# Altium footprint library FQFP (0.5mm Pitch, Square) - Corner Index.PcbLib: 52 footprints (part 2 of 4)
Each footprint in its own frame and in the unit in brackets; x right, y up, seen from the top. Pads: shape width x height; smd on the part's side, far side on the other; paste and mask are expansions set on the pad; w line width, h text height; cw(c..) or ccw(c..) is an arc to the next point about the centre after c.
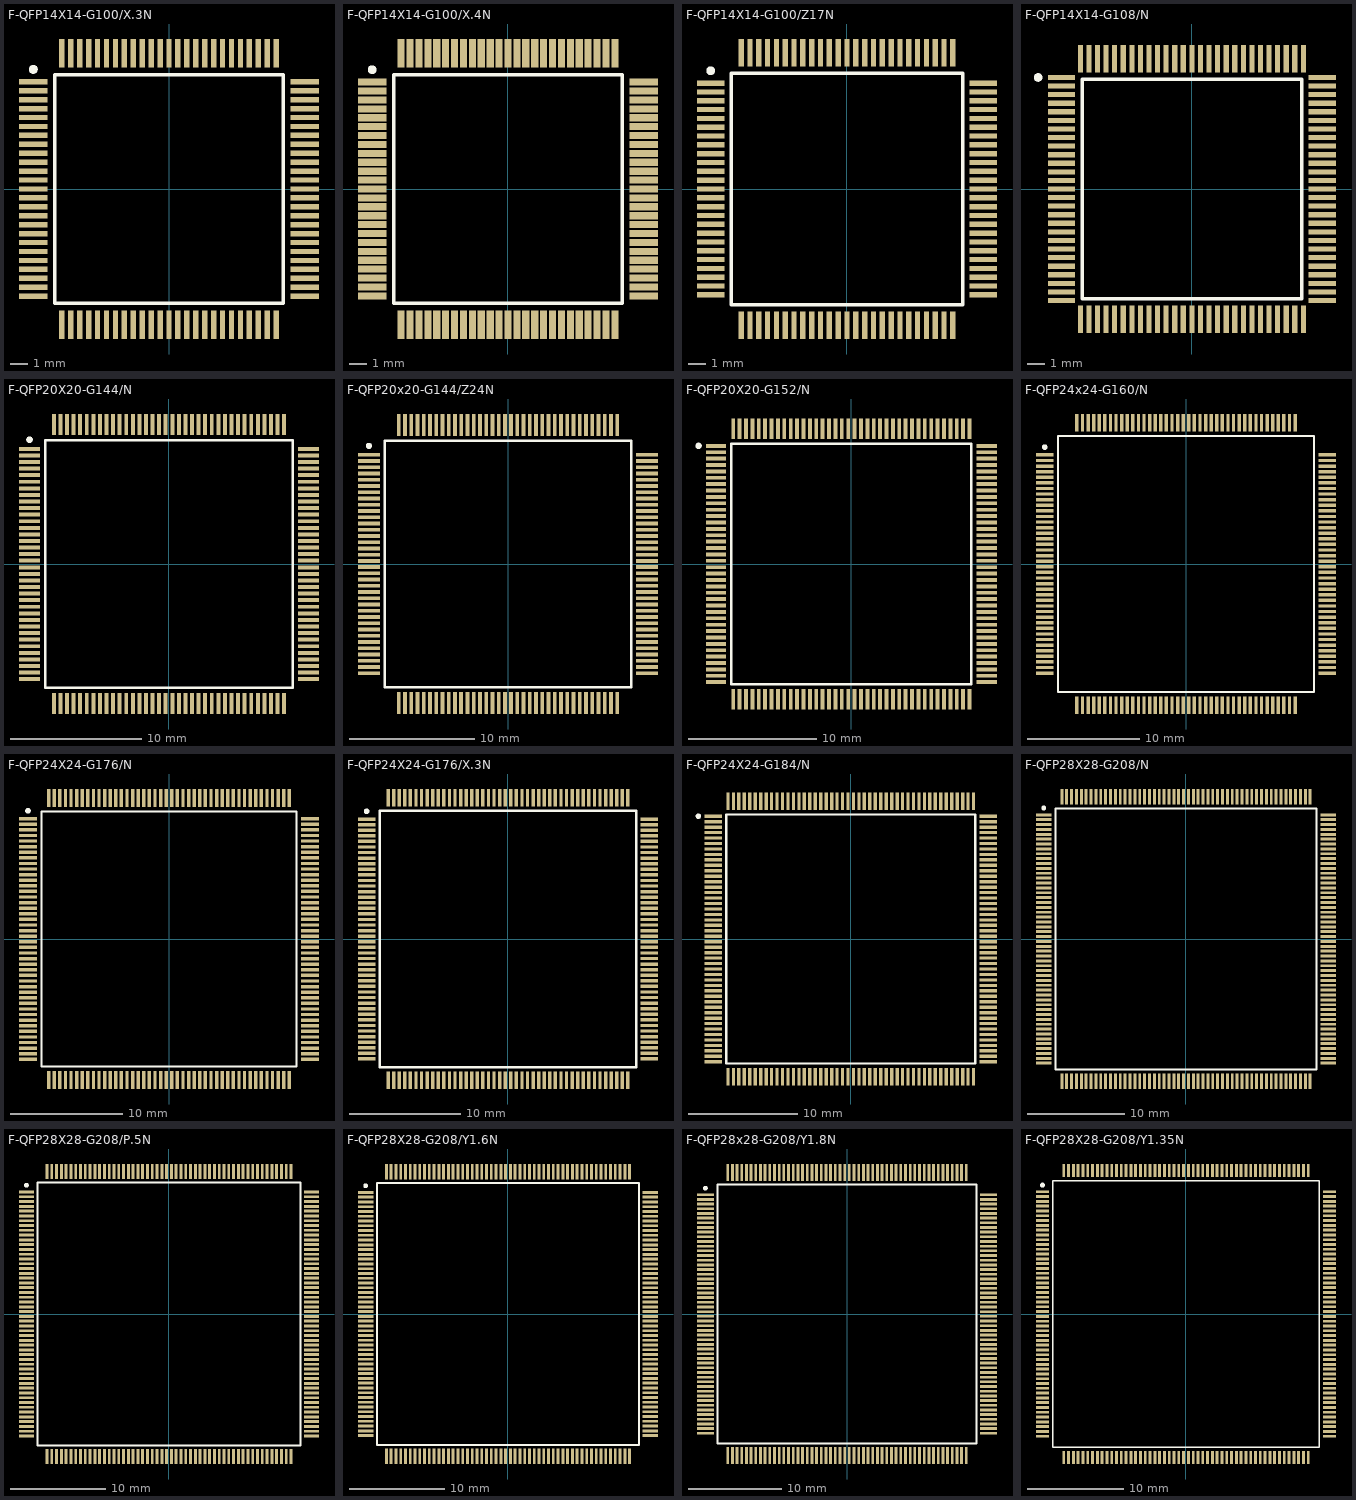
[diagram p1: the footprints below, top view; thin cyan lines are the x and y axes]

## F-QFP14X14-G100/X.3N [mm]
pads (100):
  rect 1.6x0.3 smd: 1(-7.6,6) 2(-7.6,5.5) 3(-7.6,5) 4(-7.6,4.5) 5(-7.6,4) 6(-7.6,3.5) 7(-7.6,3) 8(-7.6,2.5) 9(-7.6,2) 10(-7.6,1.5) 11(-7.6,1) 12(-7.6,0.5) 13(-7.6,0) 14(-7.6,-0.5) 15(-7.6,-1) 16(-7.6,-1.5) 17(-7.6,-2) 18(-7.6,-2.5) 19(-7.6,-3) 20(-7.6,-3.5) 21(-7.6,-4) 22(-7.6,-4.5) 23(-7.6,-5) 24(-7.6,-5.5) 25(-7.6,-6) 51(7.6,-6) 52(7.6,-5.5) 53(7.6,-5) 54(7.6,-4.5) 55(7.6,-4) 56(7.6,-3.5) 57(7.6,-3) 58(7.6,-2.5) 59(7.6,-2) 60(7.6,-1.5) 61(7.6,-1) 62(7.6,-0.5) 63(7.6,0) 64(7.6,0.5) 65(7.6,1) 66(7.6,1.5) 67(7.6,2) 68(7.6,2.5) 69(7.6,3) 70(7.6,3.5) 71(7.6,4) 72(7.6,4.5) 73(7.6,5) 74(7.6,5.5) 75(7.6,6)
  rect 0.3x1.6 smd: 26(-6,-7.6) 27(-5.5,-7.6) 28(-5,-7.6) 29(-4.5,-7.6) 30(-4,-7.6) 31(-3.5,-7.6) 32(-3,-7.6) 33(-2.5,-7.6) 34(-2,-7.6) 35(-1.5,-7.6) 36(-1,-7.6) 37(-0.5,-7.6) 38(0,-7.6) 39(0.5,-7.6) 40(1,-7.6) 41(1.5,-7.6) 42(2,-7.6) 43(2.5,-7.6) 44(3,-7.6) 45(3.5,-7.6) 46(4,-7.6) 47(4.5,-7.6) 48(5,-7.6) 49(5.5,-7.6) 50(6,-7.6) 76(6,7.6) 77(5.5,7.6) 78(5,7.6) 79(4.5,7.6) 80(4,7.6) 81(3.5,7.6) 82(3,7.6) 83(2.5,7.6) 84(2,7.6) 85(1.5,7.6) 86(1,7.6) 87(0.5,7.6) 88(0,7.6) 89(-0.5,7.6) 90(-1,7.6) 91(-1.5,7.6) 92(-2,7.6) 93(-2.5,7.6) 94(-3,7.6) 95(-3.5,7.6) 96(-4,7.6) 97(-4.5,7.6) 98(-5,7.6) 99(-5.5,7.6) 100(-6,7.6)
Top Overlay:
  circle w0.25: c-7.6,6.7 r0.125
  lines w0.2: -6.4,-6.4 6.4,-6.4 6.4,6.4 -6.4,6.4 -6.4,-6.4

## F-QFP14X14-G100/X.4N [mm]
pads (100):
  rect 1.6x0.4 smd: 1(-7.625,6) 2(-7.625,5.5) 3(-7.625,5) 4(-7.625,4.5) 5(-7.625,4) 6(-7.625,3.5) 7(-7.625,3) 8(-7.625,2.5) 9(-7.625,2) 10(-7.625,1.5) 11(-7.625,1) 12(-7.625,0.5) 13(-7.625,0) 14(-7.625,-0.5) 15(-7.625,-1) 16(-7.625,-1.5) 17(-7.625,-2) 18(-7.625,-2.5) 19(-7.625,-3) 20(-7.625,-3.5) 21(-7.625,-4) 22(-7.625,-4.5) 23(-7.625,-5) 24(-7.625,-5.5) 25(-7.625,-6) 51(7.625,-6) 52(7.625,-5.5) 53(7.625,-5) 54(7.625,-4.5) 55(7.625,-4) 56(7.625,-3.5) 57(7.625,-3) 58(7.625,-2.5) 59(7.625,-2) 60(7.625,-1.5) 61(7.625,-1) 62(7.625,-0.5) 63(7.625,0) 64(7.625,0.5) 65(7.625,1) 66(7.625,1.5) 67(7.625,2) 68(7.625,2.5) 69(7.625,3) 70(7.625,3.5) 71(7.625,4) 72(7.625,4.5) 73(7.625,5) 74(7.625,5.5) 75(7.625,6)
  rect 0.4x1.6 smd: 26(-6,-7.625) 27(-5.5,-7.625) 28(-5,-7.625) 29(-4.5,-7.625) 30(-4,-7.625) 31(-3.5,-7.625) 32(-3,-7.625) 33(-2.5,-7.625) 34(-2,-7.625) 35(-1.5,-7.625) 36(-1,-7.625) 37(-0.5,-7.625) 38(0,-7.625) 39(0.5,-7.625) 40(1,-7.625) 41(1.5,-7.625) 42(2,-7.625) 43(2.5,-7.625) 44(3,-7.625) 45(3.5,-7.625) 46(4,-7.625) 47(4.5,-7.625) 48(5,-7.625) 49(5.5,-7.625) 50(6,-7.625) 76(6,7.625) 77(5.5,7.625) 78(5,7.625) 79(4.5,7.625) 80(4,7.625) 81(3.5,7.625) 82(3,7.625) 83(2.5,7.625) 84(2,7.625) 85(1.5,7.625) 86(1,7.625) 87(0.5,7.625) 88(0,7.625) 89(-0.5,7.625) 90(-1,7.625) 91(-1.5,7.625) 92(-2,7.625) 93(-2.5,7.625) 94(-3,7.625) 95(-3.5,7.625) 96(-4,7.625) 97(-4.5,7.625) 98(-5,7.625) 99(-5.5,7.625) 100(-6,7.625)
Top Overlay:
  circle w0.25: c-7.625,6.7 r0.125
  lines w0.2: -6.425,-6.425 6.425,-6.425 6.425,6.425 -6.425,6.425 -6.425,-6.425

## F-QFP14X14-G100/Z17N [mm]
pads (100):
  rect 1.55x0.3 smd: 1(-7.725,6) 2(-7.725,5.5) 3(-7.725,5) 4(-7.725,4.5) 5(-7.725,4) 6(-7.725,3.5) 7(-7.725,3) 8(-7.725,2.5) 9(-7.725,2) 10(-7.725,1.5) 11(-7.725,1) 12(-7.725,0.5) 13(-7.725,0) 14(-7.725,-0.5) 15(-7.725,-1) 16(-7.725,-1.5) 17(-7.725,-2) 18(-7.725,-2.5) 19(-7.725,-3) 20(-7.725,-3.5) 21(-7.725,-4) 22(-7.725,-4.5) 23(-7.725,-5) 24(-7.725,-5.5) 25(-7.725,-6) 51(7.725,-6) 52(7.725,-5.5) 53(7.725,-5) 54(7.725,-4.5) 55(7.725,-4) 56(7.725,-3.5) 57(7.725,-3) 58(7.725,-2.5) 59(7.725,-2) 60(7.725,-1.5) 61(7.725,-1) 62(7.725,-0.5) 63(7.725,0) 64(7.725,0.5) 65(7.725,1) 66(7.725,1.5) 67(7.725,2) 68(7.725,2.5) 69(7.725,3) 70(7.725,3.5) 71(7.725,4) 72(7.725,4.5) 73(7.725,5) 74(7.725,5.5) 75(7.725,6)
  rect 0.3x1.55 smd: 26(-6,-7.725) 27(-5.5,-7.725) 28(-5,-7.725) 29(-4.5,-7.725) 30(-4,-7.725) 31(-3.5,-7.725) 32(-3,-7.725) 33(-2.5,-7.725) 34(-2,-7.725) 35(-1.5,-7.725) 36(-1,-7.725) 37(-0.5,-7.725) 38(0,-7.725) 39(0.5,-7.725) 40(1,-7.725) 41(1.5,-7.725) 42(2,-7.725) 43(2.5,-7.725) 44(3,-7.725) 45(3.5,-7.725) 46(4,-7.725) 47(4.5,-7.725) 48(5,-7.725) 49(5.5,-7.725) 50(6,-7.725) 76(6,7.725) 77(5.5,7.725) 78(5,7.725) 79(4.5,7.725) 80(4,7.725) 81(3.5,7.725) 82(3,7.725) 83(2.5,7.725) 84(2,7.725) 85(1.5,7.725) 86(1,7.725) 87(0.5,7.725) 88(0,7.725) 89(-0.5,7.725) 90(-1,7.725) 91(-1.5,7.725) 92(-2,7.725) 93(-2.5,7.725) 94(-3,7.725) 95(-3.5,7.725) 96(-4,7.725) 97(-4.5,7.725) 98(-5,7.725) 99(-5.5,7.725) 100(-6,7.725)
Top Overlay:
  circle w0.25: c-7.725,6.7 r0.125
  lines w0.2: -6.55,-6.55 6.55,-6.55 6.55,6.55 -6.55,6.55 -6.55,-6.55

## F-QFP14X14-G108/N [mm]
pads (108):
  rect 1.6x0.3 smd: 1(-7.6,6.5) 2(-7.6,6) 3(-7.6,5.5) 4(-7.6,5) 5(-7.6,4.5) 6(-7.6,4) 7(-7.6,3.5) 8(-7.6,3) 9(-7.6,2.5) 10(-7.6,2) 11(-7.6,1.5) 12(-7.6,1) 13(-7.6,0.5) 14(-7.6,0) 15(-7.6,-0.5) 16(-7.6,-1) 17(-7.6,-1.5) 18(-7.6,-2) 19(-7.6,-2.5) 20(-7.6,-3) 21(-7.6,-3.5) 22(-7.6,-4) 23(-7.6,-4.5) 24(-7.6,-5) 25(-7.6,-5.5) 26(-7.6,-6) 27(-7.6,-6.5) 55(7.6,-6.5) 56(7.6,-6) 57(7.6,-5.5) 58(7.6,-5) 59(7.6,-4.5) 60(7.6,-4) 61(7.6,-3.5) 62(7.6,-3) 63(7.6,-2.5) 64(7.6,-2) 65(7.6,-1.5) 66(7.6,-1) 67(7.6,-0.5) 68(7.6,0) 69(7.6,0.5) 70(7.6,1) 71(7.6,1.5) 72(7.6,2) 73(7.6,2.5) 74(7.6,3) 75(7.6,3.5) 76(7.6,4) 77(7.6,4.5) 78(7.6,5) 79(7.6,5.5) 80(7.6,6) 81(7.6,6.5)
  rect 0.3x1.6 smd: 28(-6.5,-7.6) 29(-6,-7.6) 30(-5.5,-7.6) 31(-5,-7.6) 32(-4.5,-7.6) 33(-4,-7.6) 34(-3.5,-7.6) 35(-3,-7.6) 36(-2.5,-7.6) 37(-2,-7.6) 38(-1.5,-7.6) 39(-1,-7.6) 40(-0.5,-7.6) 41(0,-7.6) 42(0.5,-7.6) 43(1,-7.6) 44(1.5,-7.6) 45(2,-7.6) 46(2.5,-7.6) 47(3,-7.6) 48(3.5,-7.6) 49(4,-7.6) 50(4.5,-7.6) 51(5,-7.6) 52(5.5,-7.6) 53(6,-7.6) 54(6.5,-7.6) 82(6.5,7.6) 83(6,7.6) 84(5.5,7.6) 85(5,7.6) 86(4.5,7.6) 87(4,7.6) 88(3.5,7.6) 89(3,7.6) 90(2.5,7.6) 91(2,7.6) 92(1.5,7.6) 93(1,7.6) 94(0.5,7.6) 95(0,7.6) 96(-0.5,7.6) 97(-1,7.6) 98(-1.5,7.6) 99(-2,7.6) 100(-2.5,7.6) 101(-3,7.6) 102(-3.5,7.6) 103(-4,7.6) 104(-4.5,7.6) 105(-5,7.6) 106(-5.5,7.6) 107(-6,7.6) 108(-6.5,7.6)
Top Overlay:
  circle w0.25: c-8.96,6.5 r0.125
  lines w0.2: -6.4,-6.4 -6.4,6.4 6.4,6.4 6.4,-6.4 -6.4,-6.4

## F-QFP20X20-G144/N [mm]
pads (144):
  rect 1.6x0.3 smd: 1(-10.6,8.75) 2(-10.6,8.25) 3(-10.6,7.75) 4(-10.6,7.25) 5(-10.6,6.75) 6(-10.6,6.25) 7(-10.6,5.75) 8(-10.6,5.25) 9(-10.6,4.75) 10(-10.6,4.25) 11(-10.6,3.75) 12(-10.6,3.25) 13(-10.6,2.75) 14(-10.6,2.25) 15(-10.6,1.75) 16(-10.6,1.25) 17(-10.6,0.75) 18(-10.6,0.25) 19(-10.6,-0.25) 20(-10.6,-0.75) 21(-10.6,-1.25) 22(-10.6,-1.75) 23(-10.6,-2.25) 24(-10.6,-2.75) 25(-10.6,-3.25) 26(-10.6,-3.75) 27(-10.6,-4.25) 28(-10.6,-4.75) 29(-10.6,-5.25) 30(-10.6,-5.75) 31(-10.6,-6.25) 32(-10.6,-6.75) 33(-10.6,-7.25) 34(-10.6,-7.75) 35(-10.6,-8.25) 36(-10.6,-8.75) 73(10.6,-8.75) 74(10.6,-8.25) 75(10.6,-7.75) 76(10.6,-7.25) 77(10.6,-6.75) 78(10.6,-6.25) 79(10.6,-5.75) 80(10.6,-5.25) 81(10.6,-4.75) 82(10.6,-4.25) 83(10.6,-3.75) 84(10.6,-3.25) 85(10.6,-2.75) 86(10.6,-2.25) 87(10.6,-1.75) 88(10.6,-1.25) 89(10.6,-0.75) 90(10.6,-0.25) 91(10.6,0.25) 92(10.6,0.75) 93(10.6,1.25) 94(10.6,1.75) 95(10.6,2.25) 96(10.6,2.75) 97(10.6,3.25) 98(10.6,3.75) 99(10.6,4.25) 100(10.6,4.75) 101(10.6,5.25) 102(10.6,5.75) 103(10.6,6.25) 104(10.6,6.75) 105(10.6,7.25) 106(10.6,7.75) 107(10.6,8.25) 108(10.6,8.75)
  rect 0.3x1.6 smd: 37(-8.75,-10.6) 38(-8.25,-10.6) 39(-7.75,-10.6) 40(-7.25,-10.6) 41(-6.75,-10.6) 42(-6.25,-10.6) 43(-5.75,-10.6) 44(-5.25,-10.6) 45(-4.75,-10.6) 46(-4.25,-10.6) 47(-3.75,-10.6) 48(-3.25,-10.6) 49(-2.75,-10.6) 50(-2.25,-10.6) 51(-1.75,-10.6) 52(-1.25,-10.6) 53(-0.75,-10.6) 54(-0.25,-10.6) 55(0.25,-10.6) 56(0.75,-10.6) 57(1.25,-10.6) 58(1.75,-10.6) 59(2.25,-10.6) 60(2.75,-10.6) 61(3.25,-10.6) 62(3.75,-10.6) 63(4.25,-10.6) 64(4.75,-10.6) 65(5.25,-10.6) 66(5.75,-10.6) 67(6.25,-10.6) 68(6.75,-10.6) 69(7.25,-10.6) 70(7.75,-10.6) 71(8.25,-10.6) 72(8.75,-10.6) 109(8.75,10.6) 110(8.25,10.6) 111(7.75,10.6) 112(7.25,10.6) 113(6.75,10.6) 114(6.25,10.6) 115(5.75,10.6) 116(5.25,10.6) 117(4.75,10.6) 118(4.25,10.6) 119(3.75,10.6) 120(3.25,10.6) 121(2.75,10.6) 122(2.25,10.6) 123(1.75,10.6) 124(1.25,10.6) 125(0.75,10.6) 126(0.25,10.6) 127(-0.25,10.6) 128(-0.75,10.6) 129(-1.25,10.6) 130(-1.75,10.6) 131(-2.25,10.6) 132(-2.75,10.6) 133(-3.25,10.6) 134(-3.75,10.6) 135(-4.25,10.6) 136(-4.75,10.6) 137(-5.25,10.6) 138(-5.75,10.6) 139(-6.25,10.6) 140(-6.75,10.6) 141(-7.25,10.6) 142(-7.75,10.6) 143(-8.25,10.6) 144(-8.75,10.6)
Top Overlay:
  circle w0.25: c-10.6,9.45 r0.125
  lines w0.2: -9.4,-9.4 -9.4,9.4 9.4,9.4 9.4,-9.4 -9.4,-9.4

## F-QFP20x20-G144/Z24N [mm]
pads (144):
  rect 1.75x0.3 smd: 1(-11.125,8.75) 2(-11.125,8.25) 3(-11.125,7.75) 4(-11.125,7.25) 5(-11.125,6.75) 6(-11.125,6.25) 7(-11.125,5.75) 8(-11.125,5.25) 9(-11.125,4.75) 10(-11.125,4.25) 11(-11.125,3.75) 12(-11.125,3.25) 13(-11.125,2.75) 14(-11.125,2.25) 15(-11.125,1.75) 16(-11.125,1.25) 17(-11.125,0.75) 18(-11.125,0.25) 19(-11.125,-0.25) 20(-11.125,-0.75) 21(-11.125,-1.25) 22(-11.125,-1.75) 23(-11.125,-2.25) 24(-11.125,-2.75) 25(-11.125,-3.25) 26(-11.125,-3.75) 27(-11.125,-4.25) 28(-11.125,-4.75) 29(-11.125,-5.25) 30(-11.125,-5.75) 31(-11.125,-6.25) 32(-11.125,-6.75) 33(-11.125,-7.25) 34(-11.125,-7.75) 35(-11.125,-8.25) 36(-11.125,-8.75) 73(11.125,-8.75) 74(11.125,-8.25) 75(11.125,-7.75) 76(11.125,-7.25) 77(11.125,-6.75) 78(11.125,-6.25) 79(11.125,-5.75) 80(11.125,-5.25) 81(11.125,-4.75) 82(11.125,-4.25) 83(11.125,-3.75) 84(11.125,-3.25) 85(11.125,-2.75) 86(11.125,-2.25) 87(11.125,-1.75) 88(11.125,-1.25) 89(11.125,-0.75) 90(11.125,-0.25) 91(11.125,0.25) 92(11.125,0.75) 93(11.125,1.25) 94(11.125,1.75) 95(11.125,2.25) 96(11.125,2.75) 97(11.125,3.25) 98(11.125,3.75) 99(11.125,4.25) 100(11.125,4.75) 101(11.125,5.25) 102(11.125,5.75) 103(11.125,6.25) 104(11.125,6.75) 105(11.125,7.25) 106(11.125,7.75) 107(11.125,8.25) 108(11.125,8.75)
  rect 0.3x1.75 smd: 37(-8.75,-11.125) 38(-8.25,-11.125) 39(-7.75,-11.125) 40(-7.25,-11.125) 41(-6.75,-11.125) 42(-6.25,-11.125) 43(-5.75,-11.125) 44(-5.25,-11.125) 45(-4.75,-11.125) 46(-4.25,-11.125) 47(-3.75,-11.125) 48(-3.25,-11.125) 49(-2.75,-11.125) 50(-2.25,-11.125) 51(-1.75,-11.125) 52(-1.25,-11.125) 53(-0.75,-11.125) 54(-0.25,-11.125) 55(0.25,-11.125) 56(0.75,-11.125) 57(1.25,-11.125) 58(1.75,-11.125) 59(2.25,-11.125) 60(2.75,-11.125) 61(3.25,-11.125) 62(3.75,-11.125) 63(4.25,-11.125) 64(4.75,-11.125) 65(5.25,-11.125) 66(5.75,-11.125) 67(6.25,-11.125) 68(6.75,-11.125) 69(7.25,-11.125) 70(7.75,-11.125) 71(8.25,-11.125) 72(8.75,-11.125) 109(8.75,11.125) 110(8.25,11.125) 111(7.75,11.125) 112(7.25,11.125) 113(6.75,11.125) 114(6.25,11.125) 115(5.75,11.125) 116(5.25,11.125) 117(4.75,11.125) 118(4.25,11.125) 119(3.75,11.125) 120(3.25,11.125) 121(2.75,11.125) 122(2.25,11.125) 123(1.75,11.125) 124(1.25,11.125) 125(0.75,11.125) 126(0.25,11.125) 127(-0.25,11.125) 128(-0.75,11.125) 129(-1.25,11.125) 130(-1.75,11.125) 131(-2.25,11.125) 132(-2.75,11.125) 133(-3.25,11.125) 134(-3.75,11.125) 135(-4.25,11.125) 136(-4.75,11.125) 137(-5.25,11.125) 138(-5.75,11.125) 139(-6.25,11.125) 140(-6.75,11.125) 141(-7.25,11.125) 142(-7.75,11.125) 143(-8.25,11.125) 144(-8.75,11.125)
Top Overlay:
  circle w0.25: c-11.13,9.45 r0.125
  lines w0.2: -9.85,-9.85 9.85,-9.85 9.85,9.85 -9.85,9.85 -9.85,-9.85

## F-QFP20X20-G152/N [mm]
pads (152):
  rect 1.6x0.3 smd: 1(-10.6,9.25) 2(-10.6,8.75) 3(-10.6,8.25) 4(-10.6,7.75) 5(-10.6,7.25) 6(-10.6,6.75) 7(-10.6,6.25) 8(-10.6,5.75) 9(-10.6,5.25) 10(-10.6,4.75) 11(-10.6,4.25) 12(-10.6,3.75) 13(-10.6,3.25) 14(-10.6,2.75) 15(-10.6,2.25) 16(-10.6,1.75) 17(-10.6,1.25) 18(-10.6,0.75) 19(-10.6,0.25) 20(-10.6,-0.25) 21(-10.6,-0.75) 22(-10.6,-1.25) 23(-10.6,-1.75) 24(-10.6,-2.25) 25(-10.6,-2.75) 26(-10.6,-3.25) 27(-10.6,-3.75) 28(-10.6,-4.25) 29(-10.6,-4.75) 30(-10.6,-5.25) 31(-10.6,-5.75) 32(-10.6,-6.25) 33(-10.6,-6.75) 34(-10.6,-7.25) 35(-10.6,-7.75) 36(-10.6,-8.25) 37(-10.6,-8.75) 38(-10.6,-9.25) 77(10.6,-9.25) 78(10.6,-8.75) 79(10.6,-8.25) 80(10.6,-7.75) 81(10.6,-7.25) 82(10.6,-6.75) 83(10.6,-6.25) 84(10.6,-5.75) 85(10.6,-5.25) 86(10.6,-4.75) 87(10.6,-4.25) 88(10.6,-3.75) 89(10.6,-3.25) 90(10.6,-2.75) 91(10.6,-2.25) 92(10.6,-1.75) 93(10.6,-1.25) 94(10.6,-0.75) 95(10.6,-0.25) 96(10.6,0.25) 97(10.6,0.75) 98(10.6,1.25) 99(10.6,1.75) 100(10.6,2.25) 101(10.6,2.75) 102(10.6,3.25) 103(10.6,3.75) 104(10.6,4.25) 105(10.6,4.75) 106(10.6,5.25) 107(10.6,5.75) 108(10.6,6.25) 109(10.6,6.75) 110(10.6,7.25) 111(10.6,7.75) 112(10.6,8.25) 113(10.6,8.75) 114(10.6,9.25)
  rect 0.3x1.6 smd: 39(-9.25,-10.6) 40(-8.75,-10.6) 41(-8.25,-10.6) 42(-7.75,-10.6) 43(-7.25,-10.6) 44(-6.75,-10.6) 45(-6.25,-10.6) 46(-5.75,-10.6) 47(-5.25,-10.6) 48(-4.75,-10.6) 49(-4.25,-10.6) 50(-3.75,-10.6) 51(-3.25,-10.6) 52(-2.75,-10.6) 53(-2.25,-10.6) 54(-1.75,-10.6) 55(-1.25,-10.6) 56(-0.75,-10.6) 57(-0.25,-10.6) 58(0.25,-10.6) 59(0.75,-10.6) 60(1.25,-10.6) 61(1.75,-10.6) 62(2.25,-10.6) 63(2.75,-10.6) 64(3.25,-10.6) 65(3.75,-10.6) 66(4.25,-10.6) 67(4.75,-10.6) 68(5.25,-10.6) 69(5.75,-10.6) 70(6.25,-10.6) 71(6.75,-10.6) 72(7.25,-10.6) 73(7.75,-10.6) 74(8.25,-10.6) 75(8.75,-10.6) 76(9.25,-10.6) 115(9.25,10.6) 116(8.75,10.6) 117(8.25,10.6) 118(7.75,10.6) 119(7.25,10.6) 120(6.75,10.6) 121(6.25,10.6) 122(5.75,10.6) 123(5.25,10.6) 124(4.75,10.6) 125(4.25,10.6) 126(3.75,10.6) 127(3.25,10.6) 128(2.75,10.6) 129(2.25,10.6) 130(1.75,10.6) 131(1.25,10.6) 132(0.75,10.6) 133(0.25,10.6) 134(-0.25,10.6) 135(-0.75,10.6) 136(-1.25,10.6) 137(-1.75,10.6) 138(-2.25,10.6) 139(-2.75,10.6) 140(-3.25,10.6) 141(-3.75,10.6) 142(-4.25,10.6) 143(-4.75,10.6) 144(-5.25,10.6) 145(-5.75,10.6) 146(-6.25,10.6) 147(-6.75,10.6) 148(-7.25,10.6) 149(-7.75,10.6) 150(-8.25,10.6) 151(-8.75,10.6) 152(-9.25,10.6)
Top Overlay:
  circle w0.25: c-11.96,9.25 r0.125
  lines w0.2: -9.4,-9.4 9.4,-9.4 9.4,9.4 -9.4,9.4 -9.4,-9.4

## F-QFP24x24-G160/N [mm]
pads (160):
  rect 1.55x0.3 smd: 1(-12.63,9.75) 2(-12.63,9.25) 3(-12.63,8.75) 4(-12.63,8.25) 5(-12.63,7.75) 6(-12.63,7.25) 7(-12.63,6.75) 8(-12.63,6.25) 9(-12.63,5.75) 10(-12.63,5.25) 11(-12.63,4.75) 12(-12.63,4.25) 13(-12.63,3.75) 14(-12.63,3.25) 15(-12.63,2.75) 16(-12.63,2.25) 17(-12.63,1.75) 18(-12.63,1.25) 19(-12.63,0.75) 20(-12.63,0.25) 21(-12.63,-0.25) 22(-12.63,-0.75) 23(-12.63,-1.25) 24(-12.63,-1.75) 25(-12.63,-2.25) 26(-12.63,-2.75) 27(-12.63,-3.25) 28(-12.63,-3.75) 29(-12.63,-4.25) 30(-12.63,-4.75) 31(-12.63,-5.25) 32(-12.63,-5.75) 33(-12.63,-6.25) 34(-12.63,-6.75) 35(-12.63,-7.25) 36(-12.63,-7.75) 37(-12.63,-8.25) 38(-12.63,-8.75) 39(-12.63,-9.25) 40(-12.63,-9.75) 81(12.63,-9.75) 82(12.63,-9.25) 83(12.63,-8.75) 84(12.63,-8.25) 85(12.63,-7.75) 86(12.63,-7.25) 87(12.63,-6.75) 88(12.63,-6.25) 89(12.63,-5.75) 90(12.63,-5.25) 91(12.63,-4.75) 92(12.63,-4.25) 93(12.63,-3.75) 94(12.63,-3.25) 95(12.63,-2.75) 96(12.63,-2.25) 97(12.63,-1.75) 98(12.63,-1.25) 99(12.63,-0.75) 100(12.63,-0.25) 101(12.63,0.25) 102(12.63,0.75) 103(12.63,1.25) 104(12.63,1.75) 105(12.63,2.25) 106(12.63,2.75) 107(12.63,3.25) 108(12.63,3.75) 109(12.63,4.25) 110(12.63,4.75) 111(12.63,5.25) 112(12.63,5.75) 113(12.63,6.25) 114(12.63,6.75) 115(12.63,7.25) 116(12.63,7.75) 117(12.63,8.25) 118(12.63,8.75) 119(12.63,9.25) 120(12.63,9.75)
  rect 0.3x1.55 smd: 41(-9.75,-12.63) 42(-9.25,-12.63) 43(-8.75,-12.63) 44(-8.25,-12.63) 45(-7.75,-12.63) 46(-7.25,-12.63) 47(-6.75,-12.63) 48(-6.25,-12.63) 49(-5.75,-12.63) 50(-5.25,-12.63) 51(-4.75,-12.63) 52(-4.25,-12.63) 53(-3.75,-12.63) 54(-3.25,-12.63) 55(-2.75,-12.63) 56(-2.25,-12.63) 57(-1.75,-12.63) 58(-1.25,-12.63) 59(-0.75,-12.63) 60(-0.25,-12.63) 61(0.25,-12.63) 62(0.75,-12.63) 63(1.25,-12.63) 64(1.75,-12.63) 65(2.25,-12.63) 66(2.75,-12.63) 67(3.25,-12.63) 68(3.75,-12.63) 69(4.25,-12.63) 70(4.75,-12.63) 71(5.25,-12.63) 72(5.75,-12.63) 73(6.25,-12.63) 74(6.75,-12.63) 75(7.25,-12.63) 76(7.75,-12.63) 77(8.25,-12.63) 78(8.75,-12.63) 79(9.25,-12.63) 80(9.75,-12.63) 121(9.75,12.63) 122(9.25,12.63) 123(8.75,12.63) 124(8.25,12.63) 125(7.75,12.63) 126(7.25,12.63) 127(6.75,12.63) 128(6.25,12.63) 129(5.75,12.63) 130(5.25,12.63) 131(4.75,12.63) 132(4.25,12.63) 133(3.75,12.63) 134(3.25,12.63) 135(2.75,12.63) 136(2.25,12.63) 137(1.75,12.63) 138(1.25,12.63) 139(0.75,12.63) 140(0.25,12.63) 141(-0.25,12.63) 142(-0.75,12.63) 143(-1.25,12.63) 144(-1.75,12.63) 145(-2.25,12.63) 146(-2.75,12.63) 147(-3.25,12.63) 148(-3.75,12.63) 149(-4.25,12.63) 150(-4.75,12.63) 151(-5.25,12.63) 152(-5.75,12.63) 153(-6.25,12.63) 154(-6.75,12.63) 155(-7.25,12.63) 156(-7.75,12.63) 157(-8.25,12.63) 158(-8.75,12.63) 159(-9.25,12.63) 160(-9.75,12.63)
Top Overlay:
  circle w0.25: c-12.63,10.45 r0.125
  lines w0.2: -11.45,-11.45 -11.45,11.45 11.45,11.45 11.45,-11.45 -11.45,-11.45

## F-QFP24X24-G176/N [mm]
pads (176):
  rect 1.6x0.3 smd: 1(-12.6,10.75) 2(-12.6,10.25) 3(-12.6,9.75) 4(-12.6,9.25) 5(-12.6,8.75) 6(-12.6,8.25) 7(-12.6,7.75) 8(-12.6,7.25) 9(-12.6,6.75) 10(-12.6,6.25) 11(-12.6,5.75) 12(-12.6,5.25) 13(-12.6,4.75) 14(-12.6,4.25) 15(-12.6,3.75) 16(-12.6,3.25) 17(-12.6,2.75) 18(-12.6,2.25) 19(-12.6,1.75) 20(-12.6,1.25) 21(-12.6,0.75) 22(-12.6,0.25) 23(-12.6,-0.25) 24(-12.6,-0.75) 25(-12.6,-1.25) 26(-12.6,-1.75) 27(-12.6,-2.25) 28(-12.6,-2.75) 29(-12.6,-3.25) 30(-12.6,-3.75) 31(-12.6,-4.25) 32(-12.6,-4.75) 33(-12.6,-5.25) 34(-12.6,-5.75) 35(-12.6,-6.25) 36(-12.6,-6.75) 37(-12.6,-7.25) 38(-12.6,-7.75) 39(-12.6,-8.25) 40(-12.6,-8.75) 41(-12.6,-9.25) 42(-12.6,-9.75) 43(-12.6,-10.25) 44(-12.6,-10.75) 89(12.6,-10.75) 90(12.6,-10.25) 91(12.6,-9.75) 92(12.6,-9.25) 93(12.6,-8.75) 94(12.6,-8.25) 95(12.6,-7.75) 96(12.6,-7.25) 97(12.6,-6.75) 98(12.6,-6.25) 99(12.6,-5.75) 100(12.6,-5.25) 101(12.6,-4.75) 102(12.6,-4.25) 103(12.6,-3.75) 104(12.6,-3.25) 105(12.6,-2.75) 106(12.6,-2.25) 107(12.6,-1.75) 108(12.6,-1.25) 109(12.6,-0.75) 110(12.6,-0.25) 111(12.6,0.25) 112(12.6,0.75) 113(12.6,1.25) 114(12.6,1.75) 115(12.6,2.25) 116(12.6,2.75) 117(12.6,3.25) 118(12.6,3.75) 119(12.6,4.25) 120(12.6,4.75) 121(12.6,5.25) 122(12.6,5.75) 123(12.6,6.25) 124(12.6,6.75) 125(12.6,7.25) 126(12.6,7.75) 127(12.6,8.25) 128(12.6,8.75) 129(12.6,9.25) 130(12.6,9.75) 131(12.6,10.25) 132(12.6,10.75)
  rect 0.3x1.6 smd: 45(-10.75,-12.6) 46(-10.25,-12.6) 47(-9.75,-12.6) 48(-9.25,-12.6) 49(-8.75,-12.6) 50(-8.25,-12.6) 51(-7.75,-12.6) 52(-7.25,-12.6) 53(-6.75,-12.6) 54(-6.25,-12.6) 55(-5.75,-12.6) 56(-5.25,-12.6) 57(-4.75,-12.6) 58(-4.25,-12.6) 59(-3.75,-12.6) 60(-3.25,-12.6) 61(-2.75,-12.6) 62(-2.25,-12.6) 63(-1.75,-12.6) 64(-1.25,-12.6) 65(-0.75,-12.6) 66(-0.25,-12.6) 67(0.25,-12.6) 68(0.75,-12.6) 69(1.25,-12.6) 70(1.75,-12.6) 71(2.25,-12.6) 72(2.75,-12.6) 73(3.25,-12.6) 74(3.75,-12.6) 75(4.25,-12.6) 76(4.75,-12.6) 77(5.25,-12.6) 78(5.75,-12.6) 79(6.25,-12.6) 80(6.75,-12.6) 81(7.25,-12.6) 82(7.75,-12.6) 83(8.25,-12.6) 84(8.75,-12.6) 85(9.25,-12.6) 86(9.75,-12.6) 87(10.25,-12.6) 88(10.75,-12.6) 133(10.75,12.6) 134(10.25,12.6) 135(9.75,12.6) 136(9.25,12.6) 137(8.75,12.6) 138(8.25,12.6) 139(7.75,12.6) 140(7.25,12.6) 141(6.75,12.6) 142(6.25,12.6) 143(5.75,12.6) 144(5.25,12.6) 145(4.75,12.6) 146(4.25,12.6) 147(3.75,12.6) 148(3.25,12.6) 149(2.75,12.6) 150(2.25,12.6) 151(1.75,12.6) 152(1.25,12.6) 153(0.75,12.6) 154(0.25,12.6) 155(-0.25,12.6) 156(-0.75,12.6) 157(-1.25,12.6) 158(-1.75,12.6) 159(-2.25,12.6) 160(-2.75,12.6) 161(-3.25,12.6) 162(-3.75,12.6) 163(-4.25,12.6) 164(-4.75,12.6) 165(-5.25,12.6) 166(-5.75,12.6) 167(-6.25,12.6) 168(-6.75,12.6) 169(-7.25,12.6) 170(-7.75,12.6) 171(-8.25,12.6) 172(-8.75,12.6) 173(-9.25,12.6) 174(-9.75,12.6) 175(-10.25,12.6) 176(-10.75,12.6)
Top Overlay:
  circle w0.25: c-12.6,11.45 r0.125
  lines w0.2: -11.4,-11.4 -11.4,11.4 11.4,11.4 11.4,-11.4 -11.4,-11.4

## F-QFP24X24-G176/X.3N [mm]
pads (176):
  rect 1.55x0.3 smd: 1(-12.675,10.75) 2(-12.675,10.25) 3(-12.675,9.75) 4(-12.675,9.25) 5(-12.675,8.75) 6(-12.675,8.25) 7(-12.675,7.75) 8(-12.675,7.25) 9(-12.675,6.75) 10(-12.675,6.25) 11(-12.675,5.75) 12(-12.675,5.25) 13(-12.675,4.75) 14(-12.675,4.25) 15(-12.675,3.75) 16(-12.675,3.25) 17(-12.675,2.75) 18(-12.675,2.25) 19(-12.675,1.75) 20(-12.675,1.25) 21(-12.675,0.75) 22(-12.675,0.25) 23(-12.675,-0.25) 24(-12.675,-0.75) 25(-12.675,-1.25) 26(-12.675,-1.75) 27(-12.675,-2.25) 28(-12.675,-2.75) 29(-12.675,-3.25) 30(-12.675,-3.75) 31(-12.675,-4.25) 32(-12.675,-4.75) 33(-12.675,-5.25) 34(-12.675,-5.75) 35(-12.675,-6.25) 36(-12.675,-6.75) 37(-12.675,-7.25) 38(-12.675,-7.75) 39(-12.675,-8.25) 40(-12.675,-8.75) 41(-12.675,-9.25) 42(-12.675,-9.75) 43(-12.675,-10.25) 44(-12.675,-10.75) 89(12.675,-10.75) 90(12.675,-10.25) 91(12.675,-9.75) 92(12.675,-9.25) 93(12.675,-8.75) 94(12.675,-8.25) 95(12.675,-7.75) 96(12.675,-7.25) 97(12.675,-6.75) 98(12.675,-6.25) 99(12.675,-5.75) 100(12.675,-5.25) 101(12.675,-4.75) 102(12.675,-4.25) 103(12.675,-3.75) 104(12.675,-3.25) 105(12.675,-2.75) 106(12.675,-2.25) 107(12.675,-1.75) 108(12.675,-1.25) 109(12.675,-0.75) 110(12.675,-0.25) 111(12.675,0.25) 112(12.675,0.75) 113(12.675,1.25) 114(12.675,1.75) 115(12.675,2.25) 116(12.675,2.75) 117(12.675,3.25) 118(12.675,3.75) 119(12.675,4.25) 120(12.675,4.75) 121(12.675,5.25) 122(12.675,5.75) 123(12.675,6.25) 124(12.675,6.75) 125(12.675,7.25) 126(12.675,7.75) 127(12.675,8.25) 128(12.675,8.75) 129(12.675,9.25) 130(12.675,9.75) 131(12.675,10.25) 132(12.675,10.75)
  rect 0.3x1.55 smd: 45(-10.75,-12.675) 46(-10.25,-12.675) 47(-9.75,-12.675) 48(-9.25,-12.675) 49(-8.75,-12.675) 50(-8.25,-12.675) 51(-7.75,-12.675) 52(-7.25,-12.675) 53(-6.75,-12.675) 54(-6.25,-12.675) 55(-5.75,-12.675) 56(-5.25,-12.675) 57(-4.75,-12.675) 58(-4.25,-12.675) 59(-3.75,-12.675) 60(-3.25,-12.675) 61(-2.75,-12.675) 62(-2.25,-12.675) 63(-1.75,-12.675) 64(-1.25,-12.675) 65(-0.75,-12.675) 66(-0.25,-12.675) 67(0.25,-12.675) 68(0.75,-12.675) 69(1.25,-12.675) 70(1.75,-12.675) 71(2.25,-12.675) 72(2.75,-12.675) 73(3.25,-12.675) 74(3.75,-12.675) 75(4.25,-12.675) 76(4.75,-12.675) 77(5.25,-12.675) 78(5.75,-12.675) 79(6.25,-12.675) 80(6.75,-12.675) 81(7.25,-12.675) 82(7.75,-12.675) 83(8.25,-12.675) 84(8.75,-12.675) 85(9.25,-12.675) 86(9.75,-12.675) 87(10.25,-12.675) 88(10.75,-12.675) 133(10.75,12.675) 134(10.25,12.675) 135(9.75,12.675) 136(9.25,12.675) 137(8.75,12.675) 138(8.25,12.675) 139(7.75,12.675) 140(7.25,12.675) 141(6.75,12.675) 142(6.25,12.675) 143(5.75,12.675) 144(5.25,12.675) 145(4.75,12.675) 146(4.25,12.675) 147(3.75,12.675) 148(3.25,12.675) 149(2.75,12.675) 150(2.25,12.675) 151(1.75,12.675) 152(1.25,12.675) 153(0.75,12.675) 154(0.25,12.675) 155(-0.25,12.675) 156(-0.75,12.675) 157(-1.25,12.675) 158(-1.75,12.675) 159(-2.25,12.675) 160(-2.75,12.675) 161(-3.25,12.675) 162(-3.75,12.675) 163(-4.25,12.675) 164(-4.75,12.675) 165(-5.25,12.675) 166(-5.75,12.675) 167(-6.25,12.675) 168(-6.75,12.675) 169(-7.25,12.675) 170(-7.75,12.675) 171(-8.25,12.675) 172(-8.75,12.675) 173(-9.25,12.675) 174(-9.75,12.675) 175(-10.25,12.675) 176(-10.75,12.675)
Top Overlay:
  circle w0.25: c-12.675,11.45 r0.125
  lines w0.2: -11.5,-11.5 -11.5,11.5 11.5,11.5 11.5,-11.5 -11.5,-11.5

## F-QFP24X24-G184/N [mm]
pads (184):
  rect 1.6x0.3 smd: 1(-12.6,11.25) 2(-12.6,10.75) 3(-12.6,10.25) 4(-12.6,9.75) 5(-12.6,9.25) 6(-12.6,8.75) 7(-12.6,8.25) 8(-12.6,7.75) 9(-12.6,7.25) 10(-12.6,6.75) 11(-12.6,6.25) 12(-12.6,5.75) 13(-12.6,5.25) 14(-12.6,4.75) 15(-12.6,4.25) 16(-12.6,3.75) 17(-12.6,3.25) 18(-12.6,2.75) 19(-12.6,2.25) 20(-12.6,1.75) 21(-12.6,1.25) 22(-12.6,0.75) 23(-12.6,0.25) 24(-12.6,-0.25) 25(-12.6,-0.75) 26(-12.6,-1.25) 27(-12.6,-1.75) 28(-12.6,-2.25) 29(-12.6,-2.75) 30(-12.6,-3.25) 31(-12.6,-3.75) 32(-12.6,-4.25) 33(-12.6,-4.75) 34(-12.6,-5.25) 35(-12.6,-5.75) 36(-12.6,-6.25) 37(-12.6,-6.75) 38(-12.6,-7.25) 39(-12.6,-7.75) 40(-12.6,-8.25) 41(-12.6,-8.75) 42(-12.6,-9.25) 43(-12.6,-9.75) 44(-12.6,-10.25) 45(-12.6,-10.75) 46(-12.6,-11.25) 93(12.6,-11.25) 94(12.6,-10.75) 95(12.6,-10.25) 96(12.6,-9.75) 97(12.6,-9.25) 98(12.6,-8.75) 99(12.6,-8.25) 100(12.6,-7.75) 101(12.6,-7.25) 102(12.6,-6.75) 103(12.6,-6.25) 104(12.6,-5.75) 105(12.6,-5.25) 106(12.6,-4.75) 107(12.6,-4.25) 108(12.6,-3.75) 109(12.6,-3.25) 110(12.6,-2.75) 111(12.6,-2.25) 112(12.6,-1.75) 113(12.6,-1.25) 114(12.6,-0.75) 115(12.6,-0.25) 116(12.6,0.25) 117(12.6,0.75) 118(12.6,1.25) 119(12.6,1.75) 120(12.6,2.25) 121(12.6,2.75) 122(12.6,3.25) 123(12.6,3.75) 124(12.6,4.25) 125(12.6,4.75) 126(12.6,5.25) 127(12.6,5.75) 128(12.6,6.25) 129(12.6,6.75) 130(12.6,7.25) 131(12.6,7.75) 132(12.6,8.25) 133(12.6,8.75) 134(12.6,9.25) 135(12.6,9.75) 136(12.6,10.25) 137(12.6,10.75) 138(12.6,11.25)
  rect 0.3x1.6 smd: 47(-11.25,-12.6) 48(-10.75,-12.6) 49(-10.25,-12.6) 50(-9.75,-12.6) 51(-9.25,-12.6) 52(-8.75,-12.6) 53(-8.25,-12.6) 54(-7.75,-12.6) 55(-7.25,-12.6) 56(-6.75,-12.6) 57(-6.25,-12.6) 58(-5.75,-12.6) 59(-5.25,-12.6) 60(-4.75,-12.6) 61(-4.25,-12.6) 62(-3.75,-12.6) 63(-3.25,-12.6) 64(-2.75,-12.6) 65(-2.25,-12.6) 66(-1.75,-12.6) 67(-1.25,-12.6) 68(-0.75,-12.6) 69(-0.25,-12.6) 70(0.25,-12.6) 71(0.75,-12.6) 72(1.25,-12.6) 73(1.75,-12.6) 74(2.25,-12.6) 75(2.75,-12.6) 76(3.25,-12.6) 77(3.75,-12.6) 78(4.25,-12.6) 79(4.75,-12.6) 80(5.25,-12.6) 81(5.75,-12.6) 82(6.25,-12.6) 83(6.75,-12.6) 84(7.25,-12.6) 85(7.75,-12.6) 86(8.25,-12.6) 87(8.75,-12.6) 88(9.25,-12.6) 89(9.75,-12.6) 90(10.25,-12.6) 91(10.75,-12.6) 92(11.25,-12.6) 139(11.25,12.6) 140(10.75,12.6) 141(10.25,12.6) 142(9.75,12.6) 143(9.25,12.6) 144(8.75,12.6) 145(8.25,12.6) 146(7.75,12.6) 147(7.25,12.6) 148(6.75,12.6) 149(6.25,12.6) 150(5.75,12.6) 151(5.25,12.6) 152(4.75,12.6) 153(4.25,12.6) 154(3.75,12.6) 155(3.25,12.6) 156(2.75,12.6) 157(2.25,12.6) 158(1.75,12.6) 159(1.25,12.6) 160(0.75,12.6) 161(0.25,12.6) 162(-0.25,12.6) 163(-0.75,12.6) 164(-1.25,12.6) 165(-1.75,12.6) 166(-2.25,12.6) 167(-2.75,12.6) 168(-3.25,12.6) 169(-3.75,12.6) 170(-4.25,12.6) 171(-4.75,12.6) 172(-5.25,12.6) 173(-5.75,12.6) 174(-6.25,12.6) 175(-6.75,12.6) 176(-7.25,12.6) 177(-7.75,12.6) 178(-8.25,12.6) 179(-8.75,12.6) 180(-9.25,12.6) 181(-9.75,12.6) 182(-10.25,12.6) 183(-10.75,12.6) 184(-11.25,12.6)
Top Overlay:
  circle w0.25: c-13.96,11.25 r0.125
  lines w0.2: -11.4,-11.4 11.4,-11.4 11.4,11.4 -11.4,11.4 -11.4,-11.4

## F-QFP28X28-G208/N [mm]
pads (208):
  rect 1.6x0.3 smd: 1(-14.6,12.75) 2(-14.6,12.25) 3(-14.6,11.75) 4(-14.6,11.25) 5(-14.6,10.75) 6(-14.6,10.25) 7(-14.6,9.75) 8(-14.6,9.25) 9(-14.6,8.75) 10(-14.6,8.25) 11(-14.6,7.75) 12(-14.6,7.25) 13(-14.6,6.75) 14(-14.6,6.25) 15(-14.6,5.75) 16(-14.6,5.25) 17(-14.6,4.75) 18(-14.6,4.25) 19(-14.6,3.75) 20(-14.6,3.25) 21(-14.6,2.75) 22(-14.6,2.25) 23(-14.6,1.75) 24(-14.6,1.25) 25(-14.6,0.75) 26(-14.6,0.25) 27(-14.6,-0.25) 28(-14.6,-0.75) 29(-14.6,-1.25) 30(-14.6,-1.75) 31(-14.6,-2.25) 32(-14.6,-2.75) 33(-14.6,-3.25) 34(-14.6,-3.75) 35(-14.6,-4.25) 36(-14.6,-4.75) 37(-14.6,-5.25) 38(-14.6,-5.75) 39(-14.6,-6.25) 40(-14.6,-6.75) 41(-14.6,-7.25) 42(-14.6,-7.75) 43(-14.6,-8.25) 44(-14.6,-8.75) 45(-14.6,-9.25) 46(-14.6,-9.75) 47(-14.6,-10.25) 48(-14.6,-10.75) 49(-14.6,-11.25) 50(-14.6,-11.75) 51(-14.6,-12.25) 52(-14.6,-12.75) 105(14.6,-12.75) 106(14.6,-12.25) 107(14.6,-11.75) 108(14.6,-11.25) 109(14.6,-10.75) 110(14.6,-10.25) 111(14.6,-9.75) 112(14.6,-9.25) 113(14.6,-8.75) 114(14.6,-8.25) 115(14.6,-7.75) 116(14.6,-7.25) 117(14.6,-6.75) 118(14.6,-6.25) 119(14.6,-5.75) 120(14.6,-5.25) 121(14.6,-4.75) 122(14.6,-4.25) 123(14.6,-3.75) 124(14.6,-3.25) 125(14.6,-2.75) 126(14.6,-2.25) 127(14.6,-1.75) 128(14.6,-1.25) 129(14.6,-0.75) 130(14.6,-0.25) 131(14.6,0.25) 132(14.6,0.75) 133(14.6,1.25) 134(14.6,1.75) 135(14.6,2.25) 136(14.6,2.75) 137(14.6,3.25) 138(14.6,3.75) 139(14.6,4.25) 140(14.6,4.75) 141(14.6,5.25) 142(14.6,5.75) 143(14.6,6.25) 144(14.6,6.75) 145(14.6,7.25) 146(14.6,7.75) 147(14.6,8.25) 148(14.6,8.75) 149(14.6,9.25) 150(14.6,9.75) 151(14.6,10.25) 152(14.6,10.75) 153(14.6,11.25) 154(14.6,11.75) 155(14.6,12.25) 156(14.6,12.75)
  rect 0.3x1.6 smd: 53(-12.75,-14.6) 54(-12.25,-14.6) 55(-11.75,-14.6) 56(-11.25,-14.6) 57(-10.75,-14.6) 58(-10.25,-14.6) 59(-9.75,-14.6) 60(-9.25,-14.6) 61(-8.75,-14.6) 62(-8.25,-14.6) 63(-7.75,-14.6) 64(-7.25,-14.6) 65(-6.75,-14.6) 66(-6.25,-14.6) 67(-5.75,-14.6) 68(-5.25,-14.6) 69(-4.75,-14.6) 70(-4.25,-14.6) 71(-3.75,-14.6) 72(-3.25,-14.6) 73(-2.75,-14.6) 74(-2.25,-14.6) 75(-1.75,-14.6) 76(-1.25,-14.6) 77(-0.75,-14.6) 78(-0.25,-14.6) 79(0.25,-14.6) 80(0.75,-14.6) 81(1.25,-14.6) 82(1.75,-14.6) 83(2.25,-14.6) 84(2.75,-14.6) 85(3.25,-14.6) 86(3.75,-14.6) 87(4.25,-14.6) 88(4.75,-14.6) 89(5.25,-14.6) 90(5.75,-14.6) 91(6.25,-14.6) 92(6.75,-14.6) 93(7.25,-14.6) 94(7.75,-14.6) 95(8.25,-14.6) 96(8.75,-14.6) 97(9.25,-14.6) 98(9.75,-14.6) 99(10.25,-14.6) 100(10.75,-14.6) 101(11.25,-14.6) 102(11.75,-14.6) 103(12.25,-14.6) 104(12.75,-14.6) 157(12.75,14.6) 158(12.25,14.6) 159(11.75,14.6) 160(11.25,14.6) 161(10.75,14.6) 162(10.25,14.6) 163(9.75,14.6) 164(9.25,14.6) 165(8.75,14.6) 166(8.25,14.6) 167(7.75,14.6) 168(7.25,14.6) 169(6.75,14.6) 170(6.25,14.6) 171(5.75,14.6) 172(5.25,14.6) 173(4.75,14.6) 174(4.25,14.6) 175(3.75,14.6) 176(3.25,14.6) 177(2.75,14.6) 178(2.25,14.6) 179(1.75,14.6) 180(1.25,14.6) 181(0.75,14.6) 182(0.25,14.6) 183(-0.25,14.6) 184(-0.75,14.6) 185(-1.25,14.6) 186(-1.75,14.6) 187(-2.25,14.6) 188(-2.75,14.6) 189(-3.25,14.6) 190(-3.75,14.6) 191(-4.25,14.6) 192(-4.75,14.6) 193(-5.25,14.6) 194(-5.75,14.6) 195(-6.25,14.6) 196(-6.75,14.6) 197(-7.25,14.6) 198(-7.75,14.6) 199(-8.25,14.6) 200(-8.75,14.6) 201(-9.25,14.6) 202(-9.75,14.6) 203(-10.25,14.6) 204(-10.75,14.6) 205(-11.25,14.6) 206(-11.75,14.6) 207(-12.25,14.6) 208(-12.75,14.6)
Top Overlay:
  circle w0.25: c-14.6,13.45 r0.125
  lines w0.2: -13.4,-13.4 13.4,-13.4 13.4,13.4 -13.4,13.4 -13.4,-13.4

## F-QFP28X28-G208/P.5N [mm]
pads (208):
  rect 1.55x0.3 smd: 1(-14.9,12.75) 2(-14.9,12.25) 3(-14.9,11.75) 4(-14.9,11.25) 5(-14.9,10.75) 6(-14.9,10.25) 7(-14.9,9.75) 8(-14.9,9.25) 9(-14.9,8.75) 10(-14.9,8.25) 11(-14.9,7.75) 12(-14.9,7.25) 13(-14.9,6.75) 14(-14.9,6.25) 15(-14.9,5.75) 16(-14.9,5.25) 17(-14.9,4.75) 18(-14.9,4.25) 19(-14.9,3.75) 20(-14.9,3.25) 21(-14.9,2.75) 22(-14.9,2.25) 23(-14.9,1.75) 24(-14.9,1.25) 25(-14.9,0.75) 26(-14.9,0.25) 27(-14.9,-0.25) 28(-14.9,-0.75) 29(-14.9,-1.25) 30(-14.9,-1.75) 31(-14.9,-2.25) 32(-14.9,-2.75) 33(-14.9,-3.25) 34(-14.9,-3.75) 35(-14.9,-4.25) 36(-14.9,-4.75) 37(-14.9,-5.25) 38(-14.9,-5.75) 39(-14.9,-6.25) 40(-14.9,-6.75) 41(-14.9,-7.25) 42(-14.9,-7.75) 43(-14.9,-8.25) 44(-14.9,-8.75) 45(-14.9,-9.25) 46(-14.9,-9.75) 47(-14.9,-10.25) 48(-14.9,-10.75) 49(-14.9,-11.25) 50(-14.9,-11.75) 51(-14.9,-12.25) 52(-14.9,-12.75) 105(14.9,-12.75) 106(14.9,-12.25) 107(14.9,-11.75) 108(14.9,-11.25) 109(14.9,-10.75) 110(14.9,-10.25) 111(14.9,-9.75) 112(14.9,-9.25) 113(14.9,-8.75) 114(14.9,-8.25) 115(14.9,-7.75) 116(14.9,-7.25) 117(14.9,-6.75) 118(14.9,-6.25) 119(14.9,-5.75) 120(14.9,-5.25) 121(14.9,-4.75) 122(14.9,-4.25) 123(14.9,-3.75) 124(14.9,-3.25) 125(14.9,-2.75) 126(14.9,-2.25) 127(14.9,-1.75) 128(14.9,-1.25) 129(14.9,-0.75) 130(14.9,-0.25) 131(14.9,0.25) 132(14.9,0.75) 133(14.9,1.25) 134(14.9,1.75) 135(14.9,2.25) 136(14.9,2.75) 137(14.9,3.25) 138(14.9,3.75) 139(14.9,4.25) 140(14.9,4.75) 141(14.9,5.25) 142(14.9,5.75) 143(14.9,6.25) 144(14.9,6.75) 145(14.9,7.25) 146(14.9,7.75) 147(14.9,8.25) 148(14.9,8.75) 149(14.9,9.25) 150(14.9,9.75) 151(14.9,10.25) 152(14.9,10.75) 153(14.9,11.25) 154(14.9,11.75) 155(14.9,12.25) 156(14.9,12.75)
  rect 0.3x1.55 smd: 53(-12.75,-14.9) 54(-12.25,-14.9) 55(-11.75,-14.9) 56(-11.25,-14.9) 57(-10.75,-14.9) 58(-10.25,-14.9) 59(-9.75,-14.9) 60(-9.25,-14.9) 61(-8.75,-14.9) 62(-8.25,-14.9) 63(-7.75,-14.9) 64(-7.25,-14.9) 65(-6.75,-14.9) 66(-6.25,-14.9) 67(-5.75,-14.9) 68(-5.25,-14.9) 69(-4.75,-14.9) 70(-4.25,-14.9) 71(-3.75,-14.9) 72(-3.25,-14.9) 73(-2.75,-14.9) 74(-2.25,-14.9) 75(-1.75,-14.9) 76(-1.25,-14.9) 77(-0.75,-14.9) 78(-0.25,-14.9) 79(0.25,-14.9) 80(0.75,-14.9) 81(1.25,-14.9) 82(1.75,-14.9) 83(2.25,-14.9) 84(2.75,-14.9) 85(3.25,-14.9) 86(3.75,-14.9) 87(4.25,-14.9) 88(4.75,-14.9) 89(5.25,-14.9) 90(5.75,-14.9) 91(6.25,-14.9) 92(6.75,-14.9) 93(7.25,-14.9) 94(7.75,-14.9) 95(8.25,-14.9) 96(8.75,-14.9) 97(9.25,-14.9) 98(9.75,-14.9) 99(10.25,-14.9) 100(10.75,-14.9) 101(11.25,-14.9) 102(11.75,-14.9) 103(12.25,-14.9) 104(12.75,-14.9) 157(12.75,14.9) 158(12.25,14.9) 159(11.75,14.9) 160(11.25,14.9) 161(10.75,14.9) 162(10.25,14.9) 163(9.75,14.9) 164(9.25,14.9) 165(8.75,14.9) 166(8.25,14.9) 167(7.75,14.9) 168(7.25,14.9) 169(6.75,14.9) 170(6.25,14.9) 171(5.75,14.9) 172(5.25,14.9) 173(4.75,14.9) 174(4.25,14.9) 175(3.75,14.9) 176(3.25,14.9) 177(2.75,14.9) 178(2.25,14.9) 179(1.75,14.9) 180(1.25,14.9) 181(0.75,14.9) 182(0.25,14.9) 183(-0.25,14.9) 184(-0.75,14.9) 185(-1.25,14.9) 186(-1.75,14.9) 187(-2.25,14.9) 188(-2.75,14.9) 189(-3.25,14.9) 190(-3.75,14.9) 191(-4.25,14.9) 192(-4.75,14.9) 193(-5.25,14.9) 194(-5.75,14.9) 195(-6.25,14.9) 196(-6.75,14.9) 197(-7.25,14.9) 198(-7.75,14.9) 199(-8.25,14.9) 200(-8.75,14.9) 201(-9.25,14.9) 202(-9.75,14.9) 203(-10.25,14.9) 204(-10.75,14.9) 205(-11.25,14.9) 206(-11.75,14.9) 207(-12.25,14.9) 208(-12.75,14.9)
Top Overlay:
  circle w0.25: c-14.9,13.45 r0.125
  lines w0.2: -13.725,-13.725 -13.725,13.725 13.725,13.725 13.725,-13.725 -13.725,-13.725

## F-QFP28X28-G208/Y1.6N [mm]
pads (208):
  rect 1.6x0.3 smd: 1(-14.925,12.75) 2(-14.925,12.25) 3(-14.925,11.75) 4(-14.925,11.25) 5(-14.925,10.75) 6(-14.925,10.25) 7(-14.925,9.75) 8(-14.925,9.25) 9(-14.925,8.75) 10(-14.925,8.25) 11(-14.925,7.75) 12(-14.925,7.25) 13(-14.925,6.75) 14(-14.925,6.25) 15(-14.925,5.75) 16(-14.925,5.25) 17(-14.925,4.75) 18(-14.925,4.25) 19(-14.925,3.75) 20(-14.925,3.25) 21(-14.925,2.75) 22(-14.925,2.25) 23(-14.925,1.75) 24(-14.925,1.25) 25(-14.925,0.75) 26(-14.925,0.25) 27(-14.925,-0.25) 28(-14.925,-0.75) 29(-14.925,-1.25) 30(-14.925,-1.75) 31(-14.925,-2.25) 32(-14.925,-2.75) 33(-14.925,-3.25) 34(-14.925,-3.75) 35(-14.925,-4.25) 36(-14.925,-4.75) 37(-14.925,-5.25) 38(-14.925,-5.75) 39(-14.925,-6.25) 40(-14.925,-6.75) 41(-14.925,-7.25) 42(-14.925,-7.75) 43(-14.925,-8.25) 44(-14.925,-8.75) 45(-14.925,-9.25) 46(-14.925,-9.75) 47(-14.925,-10.25) 48(-14.925,-10.75) 49(-14.925,-11.25) 50(-14.925,-11.75) 51(-14.925,-12.25) 52(-14.925,-12.75) 105(14.925,-12.75) 106(14.925,-12.25) 107(14.925,-11.75) 108(14.925,-11.25) 109(14.925,-10.75) 110(14.925,-10.25) 111(14.925,-9.75) 112(14.925,-9.25) 113(14.925,-8.75) 114(14.925,-8.25) 115(14.925,-7.75) 116(14.925,-7.25) 117(14.925,-6.75) 118(14.925,-6.25) 119(14.925,-5.75) 120(14.925,-5.25) 121(14.925,-4.75) 122(14.925,-4.25) 123(14.925,-3.75) 124(14.925,-3.25) 125(14.925,-2.75) 126(14.925,-2.25) 127(14.925,-1.75) 128(14.925,-1.25) 129(14.925,-0.75) 130(14.925,-0.25) 131(14.925,0.25) 132(14.925,0.75) 133(14.925,1.25) 134(14.925,1.75) 135(14.925,2.25) 136(14.925,2.75) 137(14.925,3.25) 138(14.925,3.75) 139(14.925,4.25) 140(14.925,4.75) 141(14.925,5.25) 142(14.925,5.75) 143(14.925,6.25) 144(14.925,6.75) 145(14.925,7.25) 146(14.925,7.75) 147(14.925,8.25) 148(14.925,8.75) 149(14.925,9.25) 150(14.925,9.75) 151(14.925,10.25) 152(14.925,10.75) 153(14.925,11.25) 154(14.925,11.75) 155(14.925,12.25) 156(14.925,12.75)
  rect 0.3x1.6 smd: 53(-12.75,-14.925) 54(-12.25,-14.925) 55(-11.75,-14.925) 56(-11.25,-14.925) 57(-10.75,-14.925) 58(-10.25,-14.925) 59(-9.75,-14.925) 60(-9.25,-14.925) 61(-8.75,-14.925) 62(-8.25,-14.925) 63(-7.75,-14.925) 64(-7.25,-14.925) 65(-6.75,-14.925) 66(-6.25,-14.925) 67(-5.75,-14.925) 68(-5.25,-14.925) 69(-4.75,-14.925) 70(-4.25,-14.925) 71(-3.75,-14.925) 72(-3.25,-14.925) 73(-2.75,-14.925) 74(-2.25,-14.925) 75(-1.75,-14.925) 76(-1.25,-14.925) 77(-0.75,-14.925) 78(-0.25,-14.925) 79(0.25,-14.925) 80(0.75,-14.925) 81(1.25,-14.925) 82(1.75,-14.925) 83(2.25,-14.925) 84(2.75,-14.925) 85(3.25,-14.925) 86(3.75,-14.925) 87(4.25,-14.925) 88(4.75,-14.925) 89(5.25,-14.925) 90(5.75,-14.925) 91(6.25,-14.925) 92(6.75,-14.925) 93(7.25,-14.925) 94(7.75,-14.925) 95(8.25,-14.925) 96(8.75,-14.925) 97(9.25,-14.925) 98(9.75,-14.925) 99(10.25,-14.925) 100(10.75,-14.925) 101(11.25,-14.925) 102(11.75,-14.925) 103(12.25,-14.925) 104(12.75,-14.925) 157(12.75,14.925) 158(12.25,14.925) 159(11.75,14.925) 160(11.25,14.925) 161(10.75,14.925) 162(10.25,14.925) 163(9.75,14.925) 164(9.25,14.925) 165(8.75,14.925) 166(8.25,14.925) 167(7.75,14.925) 168(7.25,14.925) 169(6.75,14.925) 170(6.25,14.925) 171(5.75,14.925) 172(5.25,14.925) 173(4.75,14.925) 174(4.25,14.925) 175(3.75,14.925) 176(3.25,14.925) 177(2.75,14.925) 178(2.25,14.925) 179(1.75,14.925) 180(1.25,14.925) 181(0.75,14.925) 182(0.25,14.925) 183(-0.25,14.925) 184(-0.75,14.925) 185(-1.25,14.925) 186(-1.75,14.925) 187(-2.25,14.925) 188(-2.75,14.925) 189(-3.25,14.925) 190(-3.75,14.925) 191(-4.25,14.925) 192(-4.75,14.925) 193(-5.25,14.925) 194(-5.75,14.925) 195(-6.25,14.925) 196(-6.75,14.925) 197(-7.25,14.925) 198(-7.75,14.925) 199(-8.25,14.925) 200(-8.75,14.925) 201(-9.25,14.925) 202(-9.75,14.925) 203(-10.25,14.925) 204(-10.75,14.925) 205(-11.25,14.925) 206(-11.75,14.925) 207(-12.25,14.925) 208(-12.75,14.925)
Top Overlay:
  circle w0.25: c-14.925,13.45 r0.125
  lines w0.2: -13.725,-13.725 13.725,-13.725 13.725,13.725 -13.725,13.725 -13.725,-13.725

## F-QFP28x28-G208/Y1.8N [mm]
pads (208):
  rect 1.8x0.3 smd: 1(-15.13,12.75) 2(-15.13,12.25) 3(-15.13,11.75) 4(-15.13,11.25) 5(-15.13,10.75) 6(-15.13,10.25) 7(-15.13,9.75) 8(-15.13,9.25) 9(-15.13,8.75) 10(-15.13,8.25) 11(-15.13,7.75) 12(-15.13,7.25) 13(-15.13,6.75) 14(-15.13,6.25) 15(-15.13,5.75) 16(-15.13,5.25) 17(-15.13,4.75) 18(-15.13,4.25) 19(-15.13,3.75) 20(-15.13,3.25) 21(-15.13,2.75) 22(-15.13,2.25) 23(-15.13,1.75) 24(-15.13,1.25) 25(-15.13,0.75) 26(-15.13,0.25) 27(-15.13,-0.25) 28(-15.13,-0.75) 29(-15.13,-1.25) 30(-15.13,-1.75) 31(-15.13,-2.25) 32(-15.13,-2.75) 33(-15.13,-3.25) 34(-15.13,-3.75) 35(-15.13,-4.25) 36(-15.13,-4.75) 37(-15.13,-5.25) 38(-15.13,-5.75) 39(-15.13,-6.25) 40(-15.13,-6.75) 41(-15.13,-7.25) 42(-15.13,-7.75) 43(-15.13,-8.25) 44(-15.13,-8.75) 45(-15.13,-9.25) 46(-15.13,-9.75) 47(-15.13,-10.25) 48(-15.13,-10.75) 49(-15.13,-11.25) 50(-15.13,-11.75) 51(-15.13,-12.25) 52(-15.13,-12.75) 105(15.13,-12.75) 106(15.13,-12.25) 107(15.13,-11.75) 108(15.13,-11.25) 109(15.13,-10.75) 110(15.13,-10.25) 111(15.13,-9.75) 112(15.13,-9.25) 113(15.13,-8.75) 114(15.13,-8.25) 115(15.13,-7.75) 116(15.13,-7.25) 117(15.13,-6.75) 118(15.13,-6.25) 119(15.13,-5.75) 120(15.13,-5.25) 121(15.13,-4.75) 122(15.13,-4.25) 123(15.13,-3.75) 124(15.13,-3.25) 125(15.13,-2.75) 126(15.13,-2.25) 127(15.13,-1.75) 128(15.13,-1.25) 129(15.13,-0.75) 130(15.13,-0.25) 131(15.13,0.25) 132(15.13,0.75) 133(15.13,1.25) 134(15.13,1.75) 135(15.13,2.25) 136(15.13,2.75) 137(15.13,3.25) 138(15.13,3.75) 139(15.13,4.25) 140(15.13,4.75) 141(15.13,5.25) 142(15.13,5.75) 143(15.13,6.25) 144(15.13,6.75) 145(15.13,7.25) 146(15.13,7.75) 147(15.13,8.25) 148(15.13,8.75) 149(15.13,9.25) 150(15.13,9.75) 151(15.13,10.25) 152(15.13,10.75) 153(15.13,11.25) 154(15.13,11.75) 155(15.13,12.25) 156(15.13,12.75)
  rect 0.3x1.8 smd: 53(-12.75,-15.13) 54(-12.25,-15.13) 55(-11.75,-15.13) 56(-11.25,-15.13) 57(-10.75,-15.13) 58(-10.25,-15.13) 59(-9.75,-15.13) 60(-9.25,-15.13) 61(-8.75,-15.13) 62(-8.25,-15.13) 63(-7.75,-15.13) 64(-7.25,-15.13) 65(-6.75,-15.13) 66(-6.25,-15.13) 67(-5.75,-15.13) 68(-5.25,-15.13) 69(-4.75,-15.13) 70(-4.25,-15.13) 71(-3.75,-15.13) 72(-3.25,-15.13) 73(-2.75,-15.13) 74(-2.25,-15.13) 75(-1.75,-15.13) 76(-1.25,-15.13) 77(-0.75,-15.13) 78(-0.25,-15.13) 79(0.25,-15.13) 80(0.75,-15.13) 81(1.25,-15.13) 82(1.75,-15.13) 83(2.25,-15.13) 84(2.75,-15.13) 85(3.25,-15.13) 86(3.75,-15.13) 87(4.25,-15.13) 88(4.75,-15.13) 89(5.25,-15.13) 90(5.75,-15.13) 91(6.25,-15.13) 92(6.75,-15.13) 93(7.25,-15.13) 94(7.75,-15.13) 95(8.25,-15.13) 96(8.75,-15.13) 97(9.25,-15.13) 98(9.75,-15.13) 99(10.25,-15.13) 100(10.75,-15.13) 101(11.25,-15.13) 102(11.75,-15.13) 103(12.25,-15.13) 104(12.75,-15.13) 157(12.75,15.13) 158(12.25,15.13) 159(11.75,15.13) 160(11.25,15.13) 161(10.75,15.13) 162(10.25,15.13) 163(9.75,15.13) 164(9.25,15.13) 165(8.75,15.13) 166(8.25,15.13) 167(7.75,15.13) 168(7.25,15.13) 169(6.75,15.13) 170(6.25,15.13) 171(5.75,15.13) 172(5.25,15.13) 173(4.75,15.13) 174(4.25,15.13) 175(3.75,15.13) 176(3.25,15.13) 177(2.75,15.13) 178(2.25,15.13) 179(1.75,15.13) 180(1.25,15.13) 181(0.75,15.13) 182(0.25,15.13) 183(-0.25,15.13) 184(-0.75,15.13) 185(-1.25,15.13) 186(-1.75,15.13) 187(-2.25,15.13) 188(-2.75,15.13) 189(-3.25,15.13) 190(-3.75,15.13) 191(-4.25,15.13) 192(-4.75,15.13) 193(-5.25,15.13) 194(-5.75,15.13) 195(-6.25,15.13) 196(-6.75,15.13) 197(-7.25,15.13) 198(-7.75,15.13) 199(-8.25,15.13) 200(-8.75,15.13) 201(-9.25,15.13) 202(-9.75,15.13) 203(-10.25,15.13) 204(-10.75,15.13) 205(-11.25,15.13) 206(-11.75,15.13) 207(-12.25,15.13) 208(-12.75,15.13)
Top Overlay:
  circle w0.25: c-15.13,13.45 r0.125
  lines w0.2: -13.825,-13.825 13.825,-13.825 13.825,13.825 -13.825,13.825 -13.825,-13.825

## F-QFP28X28-G208/Y1.35N [mm]
pads (208):
  rect 1.35x0.3 smd: 1(-14.975,12.75) 2(-14.975,12.25) 3(-14.975,11.75) 4(-14.975,11.25) 5(-14.975,10.75) 6(-14.975,10.25) 7(-14.975,9.75) 8(-14.975,9.25) 9(-14.975,8.75) 10(-14.975,8.25) 11(-14.975,7.75) 12(-14.975,7.25) 13(-14.975,6.75) 14(-14.975,6.25) 15(-14.975,5.75) 16(-14.975,5.25) 17(-14.975,4.75) 18(-14.975,4.25) 19(-14.975,3.75) 20(-14.975,3.25) 21(-14.975,2.75) 22(-14.975,2.25) 23(-14.975,1.75) 24(-14.975,1.25) 25(-14.975,0.75) 26(-14.975,0.25) 27(-14.975,-0.25) 28(-14.975,-0.75) 29(-14.975,-1.25) 30(-14.975,-1.75) 31(-14.975,-2.25) 32(-14.975,-2.75) 33(-14.975,-3.25) 34(-14.975,-3.75) 35(-14.975,-4.25) 36(-14.975,-4.75) 37(-14.975,-5.25) 38(-14.975,-5.75) 39(-14.975,-6.25) 40(-14.975,-6.75) 41(-14.975,-7.25) 42(-14.975,-7.75) 43(-14.975,-8.25) 44(-14.975,-8.75) 45(-14.975,-9.25) 46(-14.975,-9.75) 47(-14.975,-10.25) 48(-14.975,-10.75) 49(-14.975,-11.25) 50(-14.975,-11.75) 51(-14.975,-12.25) 52(-14.975,-12.75) 105(14.975,-12.75) 106(14.975,-12.25) 107(14.975,-11.75) 108(14.975,-11.25) 109(14.975,-10.75) 110(14.975,-10.25) 111(14.975,-9.75) 112(14.975,-9.25) 113(14.975,-8.75) 114(14.975,-8.25) 115(14.975,-7.75) 116(14.975,-7.25) 117(14.975,-6.75) 118(14.975,-6.25) 119(14.975,-5.75) 120(14.975,-5.25) 121(14.975,-4.75) 122(14.975,-4.25) 123(14.975,-3.75) 124(14.975,-3.25) 125(14.975,-2.75) 126(14.975,-2.25) 127(14.975,-1.75) 128(14.975,-1.25) 129(14.975,-0.75) 130(14.975,-0.25) 131(14.975,0.25) 132(14.975,0.75) 133(14.975,1.25) 134(14.975,1.75) 135(14.975,2.25) 136(14.975,2.75) 137(14.975,3.25) 138(14.975,3.75) 139(14.975,4.25) 140(14.975,4.75) 141(14.975,5.25) 142(14.975,5.75) 143(14.975,6.25) 144(14.975,6.75) 145(14.975,7.25) 146(14.975,7.75) 147(14.975,8.25) 148(14.975,8.75) 149(14.975,9.25) 150(14.975,9.75) 151(14.975,10.25) 152(14.975,10.75) 153(14.975,11.25) 154(14.975,11.75) 155(14.975,12.25) 156(14.975,12.75)
  rect 0.3x1.35 smd: 53(-12.75,-14.975) 54(-12.25,-14.975) 55(-11.75,-14.975) 56(-11.25,-14.975) 57(-10.75,-14.975) 58(-10.25,-14.975) 59(-9.75,-14.975) 60(-9.25,-14.975) 61(-8.75,-14.975) 62(-8.25,-14.975) 63(-7.75,-14.975) 64(-7.25,-14.975) 65(-6.75,-14.975) 66(-6.25,-14.975) 67(-5.75,-14.975) 68(-5.25,-14.975) 69(-4.75,-14.975) 70(-4.25,-14.975) 71(-3.75,-14.975) 72(-3.25,-14.975) 73(-2.75,-14.975) 74(-2.25,-14.975) 75(-1.75,-14.975) 76(-1.25,-14.975) 77(-0.75,-14.975) 78(-0.25,-14.975) 79(0.25,-14.975) 80(0.75,-14.975) 81(1.25,-14.975) 82(1.75,-14.975) 83(2.25,-14.975) 84(2.75,-14.975) 85(3.25,-14.975) 86(3.75,-14.975) 87(4.25,-14.975) 88(4.75,-14.975) 89(5.25,-14.975) 90(5.75,-14.975) 91(6.25,-14.975) 92(6.75,-14.975) 93(7.25,-14.975) 94(7.75,-14.975) 95(8.25,-14.975) 96(8.75,-14.975) 97(9.25,-14.975) 98(9.75,-14.975) 99(10.25,-14.975) 100(10.75,-14.975) 101(11.25,-14.975) 102(11.75,-14.975) 103(12.25,-14.975) 104(12.75,-14.975) 157(12.75,14.975) 158(12.25,14.975) 159(11.75,14.975) 160(11.25,14.975) 161(10.75,14.975) 162(10.25,14.975) 163(9.75,14.975) 164(9.25,14.975) 165(8.75,14.975) 166(8.25,14.975) 167(7.75,14.975) 168(7.25,14.975) 169(6.75,14.975) 170(6.25,14.975) 171(5.75,14.975) 172(5.25,14.975) 173(4.75,14.975) 174(4.25,14.975) 175(3.75,14.975) 176(3.25,14.975) 177(2.75,14.975) 178(2.25,14.975) 179(1.75,14.975) 180(1.25,14.975) 181(0.75,14.975) 182(0.25,14.975) 183(-0.25,14.975) 184(-0.75,14.975) 185(-1.25,14.975) 186(-1.75,14.975) 187(-2.25,14.975) 188(-2.75,14.975) 189(-3.25,14.975) 190(-3.75,14.975) 191(-4.25,14.975) 192(-4.75,14.975) 193(-5.25,14.975) 194(-5.75,14.975) 195(-6.25,14.975) 196(-6.75,14.975) 197(-7.25,14.975) 198(-7.75,14.975) 199(-8.25,14.975) 200(-8.75,14.975) 201(-9.25,14.975) 202(-9.75,14.975) 203(-10.25,14.975) 204(-10.75,14.975) 205(-11.25,14.975) 206(-11.75,14.975) 207(-12.25,14.975) 208(-12.75,14.975)
Top Overlay:
  circle w0.25: c-14.975,13.45 r0.125
  lines w0.2: -13.9,-13.9 13.9,-13.9 13.9,13.9 -13.9,13.9 -13.9,-13.9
